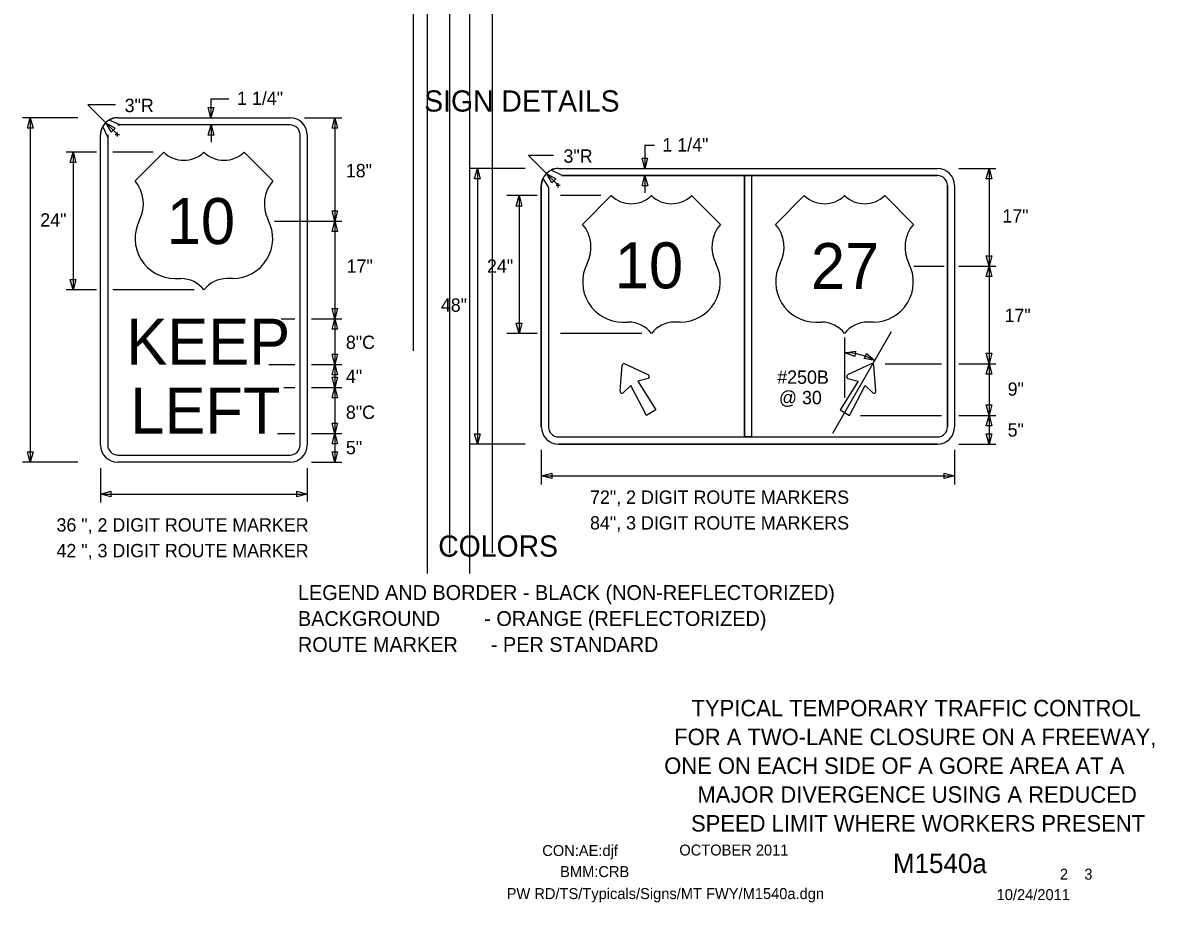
# Model space of a CAD drawing. Extents: x 16452 to 19504, y 5713 to 7079.
# Drawn here: x 17826 to 18466, y 5932 to 6430 of the extents above; entities that cross this region are included whole.
import ezdxf

# ---------------------------------------------------------------- set-up
doc = ezdxf.new("R2010")
doc.units = 0
for name, color, linetype in [('ALI_LEGAL_EX', 7, 'Continuous'), ('BORDER', 7, 'Continuous'), ('BORDER_SIGNAL_WO', 7, 'Continuous'), ('TRAFFIC_SIGNS_PR', 7, 'Continuous'), ('TYPICAL_EX', 7, 'Continuous'), ('TYPICAL_TEXT_DIMEN_PR', 7, 'Continuous')]:
    doc.layers.add(name, color=color, linetype=linetype)

msp = doc.modelspace()

# ---------------------------------------------------------------- linework, layer by layer
at = {"layer": 'ALI_LEGAL_EX'}
for p, q in [((18054.48, 7078.99), (18054.48, 6260.86)), ((18078.48, 7078.99), (18078.48, 6260.86)), ((18054.48, 6981.91), (18054.48, 6118)), ((18078.48, 6981.91), (18078.48, 6118)), ((18046.81, 6243.91), (18046.81, 6744.25)), ((18067.45, 6129.67), (18067.45, 6630.02)), ((18091.45, 6129.67), (18091.45, 6630.02))]:
    msp.add_line(p, q, dxfattribs=at)
at = {"layer": 'TRAFFIC_SIGNS_PR'}
for p, q in [((17879.4, 6375.92), (17976.9, 6375.92)), ((17871.82, 6372.3), (17870.82, 6370.79)), ((17870.84, 6370.72), (17873.72, 6364.68)), ((17880.61, 6371.86), (17874.51, 6374.6)), ((17976.9, 6371.86), (17879.4, 6371.86)), ((17869.65, 6190.67), (17869.65, 6366.17)), ((17873.72, 6366.17), (17873.72, 6190.67)), ((17982.59, 6190.67), (17982.59, 6366.17)), ((17986.65, 6366.17), (17986.65, 6190.67)), ((18130.88, 6343.17), (18124.65, 6346.19)), ((18128.92, 6347.22), (18343.42, 6347.22)), ((18128.92, 6347.22), (18343.42, 6347.22)), ((18130.86, 6343.16), (18234.14, 6343.16)), ((18343.42, 6343.16), (18130.86, 6343.16)), ((18234.14, 6343.16), (18234.14, 6195.28)), ((18238.21, 6343.16), (18238.21, 6195.28)), ((18238.21, 6343.16), (18343.42, 6343.16)), ((18119.17, 6337.47), (18119.17, 6200.97)), ((18119.17, 6200.97), (18119.17, 6337.47)), ((18120.09, 6341.48), (18123.23, 6336.44)), ((18349.11, 6337.47), (18349.11, 6291.72)), ((18349.11, 6200.97), (18349.11, 6337.47)), ((18353.17, 6337.47), (18353.17, 6200.97)), ((18353.17, 6337.47), (18353.17, 6200.97)), ((18123.24, 6336.42), (18123.24, 6200.97)), ((18123.24, 6336.42), (18123.24, 6200.97)), ((18349.11, 6291.72), (18349.11, 6200.97)), ((18163.78, 6221.08), (18164.93, 6235.8)), ((18166.44, 6236.67), (18179.75, 6230.31)), ((18305.91, 6236.67), (18292.59, 6230.31)), ((18308.57, 6221.08), (18307.42, 6235.8)), ((18128.92, 6195.28), (18343.42, 6195.28)), ((18128.92, 6191.22), (18343.42, 6191.22)), ((18343.42, 6191.22), (18128.92, 6191.22)), ((17879.4, 6184.98), (17976.9, 6184.98)), ((17976.9, 6180.92), (17879.4, 6180.92))]:
    msp.add_line(p, q, dxfattribs=at)
for points in [[(18130.86, 6343.16), (18130.85, 6343.16)], [(18123.23, 6336.44), (18123.24, 6336.42)], [(18179.59, 6228.34), (18173.87, 6226.76), (18184.09, 6210.59), (18178.69, 6207.47), (18169.79, 6224.41), (18165.57, 6220.24)], [(18292.76, 6228.34), (18298.48, 6226.76), (18288.26, 6210.59), (18293.66, 6207.47), (18302.56, 6224.41), (18306.78, 6220.24)]]:
    msp.add_lwpolyline(points, dxfattribs=at)
msp.add_lwpolyline([(18234.14, 6343.16), (18238.21, 6343.16), (18238.21, 6195.28), (18234.14, 6195.28)], close=True, dxfattribs=at)
for centre, radius, start, end in [((17879.4, 6366.17), 9.75, 90, 180), ((17878.82, 6368.34), 7.6, 85.58319, 124.53531), ((17976.9, 6366.17), 9.75, 0, 90), ((17876.69, 6366.76), 7.06, 145.86811, 184.82317), ((17880.01, 6376.28), 4.47, 262.2432, 277.7568), ((17976.9, 6366.17), 5.69, 0, 90), ((17868.26, 6365.43), 5.51, 352.24294, 7.75653), ((18128.92, 6337.47), 9.75, 90, 180), ((18128.92, 6337.47), 9.75, 90, 180), ((18128.25, 6340.65), 6.6, 84.11162, 123.06374), ((18129.86, 6350.34), 7.24, 277.81035, 278.05403), ((18343.42, 6337.47), 9.75, 0, 90), ((18343.42, 6337.47), 9.75, 0, 90), ((18343.42, 6337.47), 5.69, 0, 89.99421), ((18343.42, 6337.47), 5.69, 0, 90), ((18125.3, 6338.18), 6.17, 147.60925, 186.56283), ((18165.98, 6235.71), 1.06, 64.48226, 175.51774), ((18306.37, 6235.71), 1.06, 4.48226, 115.51774), ((18179.3, 6229.35), 1.06, 285.9885, 64.48226), ((18293.05, 6229.35), 1.06, 115.51774, 254.0115), ((18164.83, 6221), 1.06, 175.51775, 314.01151), ((18307.52, 6221), 1.06, 225.98849, 4.48225), ((18128.92, 6200.97), 9.75, 180, 270), ((18128.92, 6200.97), 9.75, 180, 270), ((18128.92, 6200.97), 5.69, 180, 270), ((18128.92, 6200.97), 5.69, 180, 270), ((18343.42, 6200.97), 9.75, 270, 0), ((18343.42, 6200.97), 5.69, 270, 0), ((18343.42, 6200.97), 9.75, 270, 0), ((18343.42, 6200.97), 5.69, 270, 0), ((17879.4, 6190.67), 9.75, 180, 270), ((17879.4, 6190.67), 5.69, 180, 270), ((17976.9, 6190.67), 5.69, 270, 0), ((17976.9, 6190.67), 9.75, 270, 0)]:
    msp.add_arc(centre, radius, start, end, dxfattribs=at)
at = {"layer": 'TYPICAL_EX'}
for p, q in [((17889.15, 6340.17), (17905.4, 6356.42)), ((17967.16, 6340.17), (17950.9, 6356.42)), ((18142.53, 6315.56), (18158.78, 6331.81)), ((18220.54, 6315.56), (18204.28, 6331.81)), ((18251.81, 6315.56), (18268.06, 6331.81)), ((18329.82, 6315.56), (18313.56, 6331.81)), ((17911.88, 6284.88), (17915.13, 6284.88)), ((17944.42, 6284.88), (17941.17, 6284.88)), ((18165.26, 6260.27), (18168.51, 6260.27)), ((18197.81, 6260.27), (18194.56, 6260.27)), ((18274.54, 6260.27), (18277.79, 6260.27)), ((18307.09, 6260.27), (18303.84, 6260.27))]:
    msp.add_line(p, q, dxfattribs=at)
for centre, radius, start, end in [((17916.78, 6368.26), 16.42, 226.14041, 313.85958), ((17939.53, 6368.26), 16.42, 226.14042, 313.85959), ((17873.75, 6327.16), 20.16, 333.09768, 40.19361), ((17982.55, 6327.16), 20.16, 139.80639, 206.90233), ((18170.16, 6343.65), 16.42, 226.14041, 313.85958), ((18192.91, 6343.65), 16.42, 226.14042, 313.85959), ((18279.44, 6343.65), 16.42, 226.14041, 313.85958), ((18302.19, 6343.65), 16.42, 226.14042, 313.85959), ((17911.92, 6307.6), 22.73, 152.6698, 269.90132), ((17944.38, 6307.6), 22.73, 270.09868, 27.3302), ((18127.13, 6302.55), 20.16, 333.09768, 40.19361), ((18235.94, 6302.55), 20.16, 139.80639, 206.90233), ((18236.41, 6302.55), 20.16, 333.09768, 40.19361), ((18345.21, 6302.55), 20.16, 139.80639, 206.90233), ((18165.3, 6282.99), 22.73, 152.6698, 269.90132), ((18197.77, 6282.99), 22.73, 270.09868, 27.3302), ((18274.58, 6282.99), 22.73, 152.6698, 269.90132), ((18307.05, 6282.99), 22.73, 270.09868, 27.3302), ((17915.17, 6268.6), 16.28, 37.1038, 90.13853), ((17941.13, 6268.6), 16.28, 89.86147, 142.8962), ((18168.55, 6243.99), 16.28, 37.1038, 90.13853), ((18194.52, 6243.99), 16.28, 89.86147, 142.8962), ((18277.83, 6243.99), 16.28, 37.1038, 90.13853), ((18303.8, 6243.99), 16.28, 89.86147, 142.8962)]:
    msp.add_arc(centre, radius, start, end, dxfattribs=at)
at = {"layer": 'TYPICAL_TEXT_DIMEN_PR'}
for p, q in [((17878.02, 6383.2), (17862.37, 6383.2)), ((17862.37, 6383.2), (17872.6, 6372.97)), ((17932.12, 6375.92), (17930.55, 6381.78)), ((17930.55, 6381.78), (17932.12, 6381.78)), ((17932.12, 6386.68), (17932.12, 6375.92)), ((17932.12, 6386.68), (17942.23, 6386.68)), ((17932.12, 6381.78), (17933.69, 6381.78)), ((17933.69, 6381.78), (17932.12, 6375.92)), ((17856.82, 6375.92), (17825.53, 6375.92)), ((17828.3, 6370.06), (17829.87, 6375.92)), ((17829.87, 6375.92), (17829.87, 6180.92)), ((17829.87, 6375.92), (17831.44, 6370.06)), ((17985.19, 6375.92), (18006.15, 6375.92)), ((18000.69, 6370.06), (18002.26, 6375.92)), ((18002.26, 6375.92), (18002.26, 6317.42)), ((18002.26, 6375.92), (18003.83, 6370.06)), ((17829.87, 6370.06), (17828.3, 6370.06)), ((17831.44, 6370.06), (17829.87, 6370.06)), ((17872.6, 6372.97), (17879.16, 6366.41)), ((17875.64, 6367.71), (17872.6, 6372.97)), ((17872.6, 6372.97), (17877.86, 6369.93)), ((17876.75, 6368.82), (17875.64, 6367.71)), ((17877.86, 6369.93), (17876.75, 6368.82)), ((17930.6, 6365.99), (17932.17, 6371.86)), ((17932.17, 6371.86), (17932.17, 6362.11)), ((17932.17, 6371.86), (17933.74, 6365.99)), ((18002.26, 6370.06), (18000.69, 6370.06)), ((18003.83, 6370.06), (18002.26, 6370.06)), ((17877.95, 6366.41), (17880.37, 6366.41)), ((17879.16, 6365.2), (17879.16, 6367.62)), ((17932.17, 6365.99), (17930.6, 6365.99)), ((17933.74, 6365.99), (17932.17, 6365.99)), ((17867.28, 6356.42), (17850.15, 6356.42)), ((17852.48, 6350.56), (17854.05, 6356.42)), ((17854.05, 6356.42), (17854.05, 6278.42)), ((17854.05, 6356.42), (17855.62, 6350.56)), ((17899.52, 6356.42), (17876.64, 6356.42)), ((18177.78, 6360.37), (18177.78, 6347.22)), ((18177.78, 6360.37), (18183.31, 6360.37)), ((17854.05, 6350.56), (17852.48, 6350.56)), ((17855.62, 6350.56), (17854.05, 6350.56)), ((18126.06, 6354.5), (18111.89, 6354.5)), ((18111.89, 6354.5), (18122.04, 6344.36)), ((18177.78, 6347.22), (18176.21, 6353.08)), ((18176.21, 6353.08), (18177.78, 6353.08)), ((18177.78, 6353.08), (18179.35, 6353.08)), ((18179.35, 6353.08), (18177.78, 6347.22)), ((18109.94, 6347.22), (18078.65, 6347.22)), ((18081.42, 6341.36), (18082.99, 6347.22)), ((18082.99, 6347.22), (18082.99, 6191.22)), ((18082.99, 6347.22), (18084.56, 6341.36)), ((18122.04, 6344.36), (18128.68, 6337.71)), ((18125.07, 6339.1), (18122.04, 6344.36)), ((18122.04, 6344.36), (18127.29, 6341.32)), ((18176.26, 6337.3), (18177.83, 6343.16)), ((18176.26, 6337.3), (18177.83, 6343.16)), ((18177.83, 6343.16), (18177.83, 6333.41)), ((18177.83, 6343.16), (18179.4, 6337.3)), ((18177.83, 6343.16), (18179.4, 6337.3)), ((18355.55, 6347.22), (18376.51, 6347.22)), ((18371.04, 6341.36), (18372.61, 6347.22)), ((18372.61, 6347.22), (18372.61, 6291.97)), ((18372.61, 6347.22), (18374.18, 6341.36)), ((18082.99, 6341.36), (18081.42, 6341.36)), ((18084.56, 6341.36), (18082.99, 6341.36)), ((18126.18, 6340.21), (18125.07, 6339.1)), ((18127.29, 6341.32), (18126.18, 6340.21)), ((18127.48, 6337.71), (18129.89, 6337.71)), ((18128.68, 6336.5), (18128.68, 6338.92)), ((18177.83, 6337.3), (18176.26, 6337.3)), ((18177.83, 6337.3), (18176.26, 6337.3)), ((18179.4, 6337.3), (18177.83, 6337.3)), ((18179.4, 6337.3), (18177.83, 6337.3)), ((18372.61, 6341.36), (18371.04, 6341.36)), ((18374.18, 6341.36), (18372.61, 6341.36)), ((18116.8, 6331.81), (18099.67, 6331.81)), ((18104.97, 6325.95), (18106.54, 6331.81)), ((18106.54, 6331.81), (18106.54, 6253.81)), ((18106.54, 6331.81), (18108.11, 6325.95)), ((18152.9, 6331.81), (18130.03, 6331.81)), ((18106.54, 6325.95), (18104.97, 6325.95)), ((18108.11, 6325.95), (18106.54, 6325.95)), ((17968.04, 6317.42), (18006.15, 6317.42)), ((18002.26, 6317.42), (18000.69, 6323.28)), ((18000.69, 6323.28), (18002.26, 6323.28)), ((18000.69, 6311.56), (18002.26, 6317.42)), ((18002.26, 6323.28), (18003.83, 6323.28)), ((18003.83, 6323.28), (18002.26, 6317.42)), ((18002.26, 6317.42), (18002.26, 6262.17)), ((18002.26, 6317.42), (18003.83, 6311.56)), ((18002.26, 6311.56), (18000.69, 6311.56)), ((18003.83, 6311.56), (18002.26, 6311.56)), ((18329.99, 6291.97), (18347.14, 6291.97)), ((18355.55, 6291.97), (18376.51, 6291.97)), ((18372.61, 6291.97), (18371.04, 6297.83)), ((18371.04, 6297.83), (18372.61, 6297.83)), ((18371.04, 6286.11), (18372.61, 6291.97)), ((18372.61, 6297.83), (18374.18, 6297.83)), ((18374.18, 6297.83), (18372.61, 6291.97)), ((18372.61, 6291.97), (18372.61, 6236.72)), ((18372.61, 6291.97), (18374.18, 6286.11)), ((18372.61, 6286.11), (18371.04, 6286.11)), ((18374.18, 6286.11), (18372.61, 6286.11)), ((17854.05, 6278.42), (17852.48, 6284.28)), ((17852.48, 6284.28), (17854.05, 6284.28)), ((17854.05, 6284.28), (17855.62, 6284.28)), ((17855.62, 6284.28), (17854.05, 6278.42)), ((17867.28, 6278.42), (17850.15, 6278.42)), ((17922.64, 6278.42), (17876.64, 6278.42)), ((18002.26, 6262.17), (18000.69, 6268.03)), ((18000.69, 6268.03), (18002.26, 6268.03)), ((18002.26, 6268.03), (18003.83, 6268.03)), ((18003.83, 6268.03), (18002.26, 6262.17)), ((17971.98, 6262.17), (17979.66, 6262.17)), ((17989.03, 6262.17), (18006.15, 6262.17)), ((18000.69, 6256.31), (18002.26, 6262.17)), ((18002.26, 6262.17), (18002.26, 6236.17)), ((18002.26, 6262.17), (18003.83, 6256.31)), ((18106.54, 6253.81), (18104.97, 6259.67)), ((18104.97, 6259.67), (18106.54, 6259.67)), ((18106.54, 6259.67), (18108.11, 6259.67)), ((18108.11, 6259.67), (18106.54, 6253.81)), ((18002.26, 6256.31), (18000.69, 6256.31)), ((18003.83, 6256.31), (18002.26, 6256.31)), ((18116.8, 6253.81), (18099.67, 6253.81)), ((18176.03, 6253.81), (18130.03, 6253.81)), ((18284.21, 6197.32), (18317.45, 6254.91)), ((18290.96, 6217.48), (18290.96, 6251.47)), ((18002.26, 6236.17), (18000.69, 6242.03)), ((18000.69, 6242.03), (18002.26, 6242.03)), ((18002.26, 6242.03), (18003.83, 6242.03)), ((18003.83, 6242.03), (18002.26, 6236.17)), ((18290.99, 6242.91), (18296.98, 6243.87)), ((18296.66, 6240.75), (18290.99, 6242.91)), ((18296.82, 6242.31), (18296.66, 6240.75)), ((18296.98, 6243.87), (18296.82, 6242.31)), ((18301.98, 6239.59), (18302.66, 6241.01)), ((18302.66, 6241.01), (18303.34, 6242.42)), ((18303.34, 6242.42), (18307.94, 6238.46)), ((18372.61, 6236.72), (18371.04, 6242.58)), ((18371.04, 6242.58), (18372.61, 6242.58)), ((18372.61, 6242.58), (18374.18, 6242.58)), ((18374.18, 6242.58), (18372.61, 6236.72)), ((17964.96, 6236.17), (17979.66, 6236.17)), ((17989.03, 6236.17), (18006.15, 6236.17)), ((18000.69, 6230.31), (18002.26, 6236.17)), ((18002.26, 6236.17), (18002.26, 6223.17)), ((18002.26, 6236.17), (18003.83, 6230.31)), ((18307.94, 6238.46), (18301.98, 6239.59)), ((18313.91, 6236.72), (18345.78, 6236.72)), ((18355.55, 6236.72), (18376.51, 6236.72)), ((18371.04, 6230.86), (18372.61, 6236.72)), ((18372.61, 6236.72), (18372.61, 6207.47)), ((18372.61, 6236.72), (18374.18, 6230.86)), ((18002.26, 6230.31), (18000.69, 6230.31)), ((18002.26, 6223.17), (18000.69, 6229.03)), ((18000.69, 6229.03), (18002.26, 6229.03)), ((18003.83, 6230.31), (18002.26, 6230.31)), ((18002.26, 6229.03), (18003.83, 6229.03)), ((18003.83, 6229.03), (18002.26, 6223.17)), ((18372.61, 6230.86), (18371.04, 6230.86)), ((18374.18, 6230.86), (18372.61, 6230.86)), ((17973.32, 6223.17), (17979.66, 6223.17)), ((17989.03, 6223.17), (18006.15, 6223.17)), ((18000.69, 6217.31), (18002.26, 6223.17)), ((18002.26, 6223.17), (18002.26, 6197.17)), ((18002.26, 6223.17), (18003.83, 6217.31)), ((18002.26, 6217.31), (18000.69, 6217.31)), ((18003.83, 6217.31), (18002.26, 6217.31)), ((18372.61, 6207.47), (18371.04, 6213.33)), ((18371.04, 6213.33), (18372.61, 6213.33)), ((18372.61, 6213.33), (18374.18, 6213.33)), ((18374.18, 6213.33), (18372.61, 6207.47)), ((18002.26, 6197.17), (18000.69, 6203.03)), ((18000.69, 6203.03), (18002.26, 6203.03)), ((18002.26, 6203.03), (18003.83, 6203.03)), ((18003.83, 6203.03), (18002.26, 6197.17)), ((18299.78, 6207.47), (18345.78, 6207.47)), ((18355.55, 6207.47), (18376.51, 6207.47)), ((18371.04, 6201.61), (18372.61, 6207.47)), ((18372.61, 6207.47), (18372.61, 6191.22)), ((18372.61, 6207.47), (18374.18, 6201.61)), ((17969.82, 6197.17), (17979.66, 6197.17)), ((17989.03, 6197.17), (18006.15, 6197.17)), ((18000.69, 6191.31), (18002.26, 6197.17)), ((18002.26, 6197.17), (18002.26, 6180.92)), ((18002.26, 6197.17), (18003.83, 6191.31)), ((18082.99, 6191.22), (18081.42, 6197.08)), ((18081.42, 6197.08), (18082.99, 6197.08)), ((18082.99, 6197.08), (18084.56, 6197.08)), ((18084.56, 6197.08), (18082.99, 6191.22)), ((18372.61, 6201.61), (18371.04, 6201.61)), ((18372.61, 6191.22), (18371.04, 6197.08)), ((18371.04, 6197.08), (18372.61, 6197.08)), ((18374.18, 6201.61), (18372.61, 6201.61)), ((18372.61, 6197.08), (18374.18, 6197.08)), ((18374.18, 6197.08), (18372.61, 6191.22)), ((18002.26, 6191.31), (18000.69, 6191.31)), ((18003.83, 6191.31), (18002.26, 6191.31)), ((18109.94, 6191.22), (18078.65, 6191.22)), ((18355.55, 6191.22), (18372.67, 6191.22)), ((18355.55, 6191.22), (18376.51, 6191.22)), ((18355.55, 6191.22), (18372.67, 6191.22)), ((17829.87, 6180.92), (17828.3, 6186.78)), ((17828.3, 6186.78), (17829.87, 6186.78)), ((17829.87, 6186.78), (17831.44, 6186.78)), ((17831.44, 6186.78), (17829.87, 6180.92)), ((18002.26, 6180.92), (18000.69, 6186.78)), ((18000.69, 6186.78), (18002.26, 6186.78)), ((18002.26, 6186.78), (18003.83, 6186.78)), ((18003.83, 6186.78), (18002.26, 6180.92)), ((18119.17, 6187.88), (18119.17, 6168.31)), ((18353.17, 6187.88), (18353.17, 6168.31)), ((17856.82, 6180.92), (17825.53, 6180.92)), ((17869.65, 6177.57), (17869.65, 6158.22)), ((17986.65, 6177.57), (17986.65, 6158.68)), ((17989.03, 6180.92), (18006.15, 6180.92)), ((18119.17, 6173.25), (18125.04, 6174.82)), ((18119.17, 6173.25), (18353.17, 6173.25)), ((18125.04, 6171.68), (18119.17, 6173.25)), ((18125.04, 6174.82), (18125.04, 6173.25)), ((18125.04, 6173.25), (18125.04, 6171.68)), ((18347.31, 6173.25), (18347.31, 6174.82)), ((18347.31, 6174.82), (18353.17, 6173.25)), ((18353.17, 6173.25), (18347.31, 6171.68)), ((18347.31, 6171.68), (18347.31, 6173.25)), ((17869.65, 6162.95), (17875.51, 6164.52)), ((17875.51, 6164.52), (17875.51, 6162.95)), ((17980.79, 6162.95), (17980.79, 6164.52)), ((17980.79, 6164.52), (17986.65, 6162.95)), ((17869.65, 6162.95), (17986.65, 6162.95)), ((17875.51, 6161.38), (17869.65, 6162.95)), ((17875.51, 6162.95), (17875.51, 6161.38)), ((17986.65, 6162.95), (17980.79, 6161.38)), ((17980.79, 6161.38), (17980.79, 6162.95))]:
    msp.add_line(p, q, dxfattribs=at)
msp.add_arc((18291.16, 6208.48), 34.39, 60.74521, 90.32117, dxfattribs=at)

# ---------------------------------------------------------------- texts
at = {"layer": 'BORDER'}
for s, p in [('TYPICAL TEMPORARY TRAFFIC CONTROL', (18204.21, 6037.14)), ('FOR A TWO-LANE CLOSURE ON A FREEWAY,', (18194.41, 6020.84)), ('ONE ON EACH SIDE OF A GORE AREA AT A ', (18188.75, 6004.54)), ('MAJOR DIVERGENCE USING A REDUCED', (18207.52, 5988.24)), ('SPEED LIMIT WHERE WORKERS PRESENT', (18203.92, 5971.94))]:
    msp.add_text(s, height=9.3, dxfattribs=at).set_placement(p)
at = {"layer": 'BORDER_SIGNAL_WO'}
for s, height, p in [('CON:AE:djf  ', 6.2, (18119.69, 5958.06)), ('    OCTOBER 2011    ', 6.2, (18188.08, 5958.34)), ('    M1540a   ', 11, (18301.86, 5948.38)), ('BMM:CRB   ', 6.2, (18129.81, 5946.17)), (' 2    3 ', 6.2, (18410.45, 5944.7)), ('PW RD/TS/Typicals/Signs/MT FWY/M1540a.dgn      ', 6.2, (18099.55, 5933.71)), ('10/24/2011    ', 6.2, (18376.93, 5933.13))]:
    msp.add_text(s, height=height, dxfattribs=at).set_placement(p)
at = {"layer": 'TRAFFIC_SIGNS_PR'}
for s, p in [('10', (17907.12, 6304.42)), ('10', (18160.77, 6279.35)), ('27', (18271.78, 6278.99)), ('KEEP', (17884.26, 6236.17)), ('LEFT', (17886.49, 6197.17))]:
    msp.add_text(s, height=26, dxfattribs=at).set_placement(p)
at = {"layer": 'TYPICAL_TEXT_DIMEN_PR'}
for s, height, p in [('1 1/4"', 7.55, (17946.93, 6383.17)), ('SIGN DETAILS', 12, (18052.88, 6379.39)), ('3"R', 7.55, (17883.29, 6379.08)), ('1 1/4"', 7.55, (18187.71, 6356.8)), ('3"R', 7.55, (18131.71, 6350.43)), ('18"', 7.55, (18008.49, 6342.19)), ('17"', 7.55, (18380.18, 6316.58)), ('24"', 7.55, (17835.5, 6314.3)), ('17"', 7.55, (18008.95, 6288.14)), ('24"', 7.55, (18088.4, 6288.14)), ('48"', 7.55, (18062.29, 6266.12)), ('17"', 7.55, (18381.39, 6260.22)), ('8"C', 7.55, (18008.53, 6245.03)), ('4" ', 7.55, (18008.53, 6225.77)), ('#250B', 7.55, (18252.73, 6225.31)), ('@ 30', 7.55, (18253.68, 6213.76)), ('9"', 7.55, (18383.17, 6218.57)), ('8"C', 7.55, (18008.53, 6205.44)), ('5"', 7.55, (18383.16, 6195.47)), ('5" ', 7.55, (18008.53, 6185.46)), ('72", 2 DIGIT ROUTE MARKERS', 7.55, (18146.75, 6157.39)), ('36 ", 2 DIGIT ROUTE MARKER', 7.55, (17844.7, 6141.69)), ('84", 3 DIGIT ROUTE MARKERS', 7.55, (18146.75, 6142.84)), ('COLORS', 12, (18060.82, 6127.5)), ('42 ", 3 DIGIT ROUTE MARKER', 7.55, (17844.7, 6127.14)), ('LEGEND AND BORDER - BLACK (NON-REFLECTORIZED)', 8.4, (17981.39, 6102.97)), ('BACKGROUND        - ORANGE (REFLECTORIZED)', 8.4, (17981.39, 6088.27)), ('ROUTE MARKER      - PER STANDARD', 8.4, (17981.39, 6073.57))]:
    msp.add_text(s, height=height, dxfattribs=at).set_placement(p)

doc.saveas('drawing.dxf')
